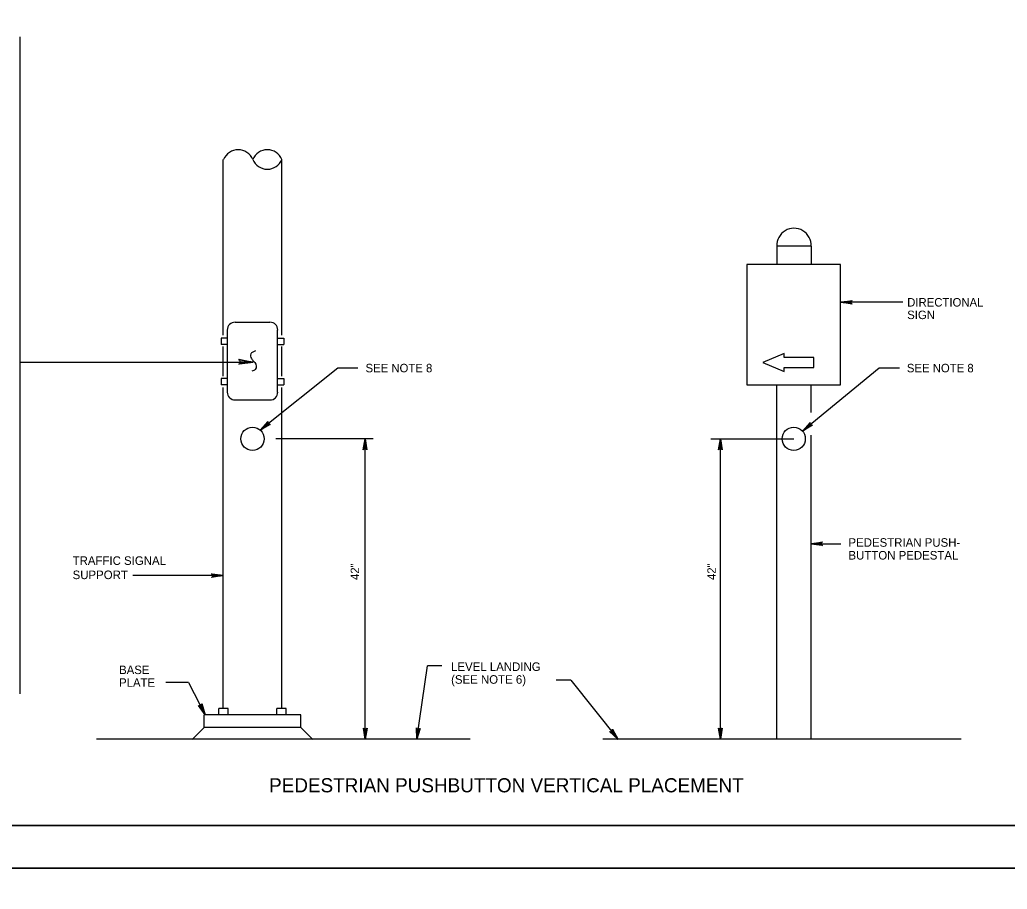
# Model space of a CAD drawing. Extents: x -344 to 940, y 22 to 1233.
# Drawn here: x 262.3 to 611.7, y 608.7 to 916.3 of the extents above; entities that cross this region are included whole.
import ezdxf

# ---------------------------------------------------------------- set-up
doc = ezdxf.new("R2010")
doc.units = 0
for name, color, linetype in [('1', 7, 'Continuous'), ('2', 7, 'Continuous'), ('3', 7, 'Continuous'), ('Default', 7, 'Continuous'), ('PLT-BNDY', 7, 'Continuous')]:
    doc.layers.add(name, color=color, linetype=linetype)

# ---------------------------------------------------------------- blocks, each defined once
blk = doc.blocks.new('RARROW')
at = {"layer": '3'}
blk.add_lwpolyline([(-2.937125, 0.36875), (-2.82775, 0.156125), (0, 0), (-2.937125, 0.36875), (-3.08775, 0.497625), (0, 0), (-2.8255, -0.13975), (-2.928625, -0.350125), (0, 0), (-3.08775, -0.490625), (-2.928625, -0.350125)], dxfattribs=at)

msp = doc.modelspace()

# ---------------------------------------------------------------- linework, layer by layer
at = {"layer": '1'}
for p, q in [((861.86, 631.17), (75.86, 631.17)), ((75.86, 631.17), (661.86, 631.17))]:
    msp.add_line(p, q, dxfattribs=at)
at = {"layer": '2'}
for p, q in [((262.33, 910.3), (262.33, 677.76)), ((334.29, 804.68), (334.29, 866.81)), ((355.04, 804.68), (355.04, 866.81)), ((530.2, 836.15), (530.2, 829.69)), ((542.29, 836.15), (530.2, 836.15)), ((542.29, 836.15), (542.29, 829.69)), ((552.75, 829.69), (519.63, 829.69)), ((519.63, 829.69), (519.63, 787.1)), ((552.75, 787.1), (552.75, 829.69)), ((350.79, 809.18), (338.54, 809.18)), ((335.79, 803.68), (333.54, 803.68)), ((333.54, 803.68), (333.54, 801.43)), ((335.79, 784.43), (335.79, 806.43)), ((353.54, 784.43), (353.54, 806.43)), ((353.54, 803.68), (355.79, 803.68)), ((355.79, 803.68), (355.79, 801.43)), ((335.79, 801.43), (333.54, 801.43)), ((334.29, 790.18), (334.29, 800.68)), ((353.54, 801.43), (355.79, 801.43)), ((355.04, 790.18), (355.04, 800.68)), ((262.33, 795.18), (344.91, 795.18)), ((374.85, 792.99), (347.38, 771.15)), ((382, 792.99), (374.85, 792.99)), ((566.39, 792.99), (539.22, 770.78)), ((573.54, 792.99), (566.39, 792.99)), ((335.79, 789.43), (333.54, 789.43)), ((333.54, 789.43), (333.54, 787.18)), ((335.79, 787.18), (333.54, 787.18)), ((334.29, 672.68), (334.29, 786.18)), ((353.54, 789.43), (355.79, 789.43)), ((353.54, 787.18), (355.79, 787.18)), ((355.04, 672.68), (355.04, 786.18)), ((355.79, 789.43), (355.79, 787.18)), ((519.63, 787.1), (552.75, 787.1)), ((530.2, 661.81), (530.2, 787.1)), ((542.29, 777.32), (542.29, 787.1)), ((350.79, 781.68), (338.54, 781.68)), ((542.29, 661.81), (542.29, 769.34)), ((387.35, 768.04), (352.97, 768.04)), ((384.54, 661.81), (384.54, 768.04)), ((506.89, 768.04), (536.17, 768.04)), ((510.22, 661.81), (510.22, 768.04)), ((542.29, 730.92), (552.81, 730.92)), ((334.29, 719.66), (302.3, 719.66)), ((402.79, 661.81), (406.54, 687.68)), ((411.66, 687.68), (406.54, 687.68)), ((322.06, 681.88), (314.03, 681.88)), ((322.06, 681.88), (327.99, 670.43)), ((457.29, 682.61), (452.17, 682.61)), ((457.29, 682.61), (474.06, 661.71)), ((336.04, 672.68), (332.79, 672.68)), ((332.79, 670.43), (332.79, 672.68)), ((336.04, 670.43), (336.04, 672.68)), ((356.54, 672.68), (353.29, 672.68)), ((353.29, 670.43), (353.29, 672.68)), ((356.54, 670.43), (356.54, 672.68)), ((327.54, 665.93), (327.54, 670.43)), ((361.79, 670.43), (327.54, 670.43)), ((361.79, 665.93), (361.79, 670.43)), ((327.54, 665.93), (323.29, 661.68)), ((361.79, 665.93), (327.54, 665.93)), ((361.79, 665.93), (366.04, 661.68)), ((421.67, 661.81), (289.51, 661.81)), ((595.39, 661.81), (468.65, 661.81))]:
    msp.add_line(p, q, dxfattribs=at)
for points in [[(556.61, 815.86), (556.47, 816.14), (552.75, 816.34), (556.61, 815.86), (556.81, 815.69), (552.75, 816.34), (556.47, 816.52), (556.6, 816.8), (552.75, 816.34), (556.81, 816.99), (556.6, 816.8)], [(340.04, 795.81), (340.16, 795.43), (344.91, 795.18), (340.04, 795.81), (339.79, 796.18), (344.91, 795.18), (340.29, 794.93), (340.04, 794.56), (344.91, 795.18), (339.79, 794.43), (340.04, 794.56)], [(350.7, 773.17), (350.42, 773.3), (347.38, 771.15), (350.7, 773.17), (350.96, 773.16), (347.38, 771.15), (350.17, 773.6), (350.11, 773.9), (347.38, 771.15), (350.16, 774.18), (350.11, 773.9)], [(542.51, 772.84), (542.22, 772.97), (539.22, 770.78), (542.51, 772.84), (542.77, 772.84), (539.22, 770.78), (541.97, 773.27), (541.9, 773.57), (539.22, 770.78), (541.95, 773.84), (541.9, 773.57)], [(546.15, 730.44), (546, 730.72), (542.29, 730.92), (546.15, 730.44), (546.34, 730.27), (542.29, 730.92), (546, 731.11), (546.13, 731.38), (542.29, 730.92), (546.34, 731.57), (546.13, 731.38)], [(330.43, 720.14), (330.57, 719.86), (334.29, 719.66), (330.43, 720.14), (330.23, 720.31), (334.29, 719.66), (330.58, 719.47), (330.44, 719.2), (334.29, 719.66), (330.23, 719.01), (330.44, 719.2)], [(326.65, 674.08), (326.47, 673.83), (327.99, 670.43), (326.65, 674.08), (326.71, 674.34), (327.99, 670.43), (326.12, 673.64), (325.81, 673.64), (327.99, 670.43), (325.55, 673.74), (325.81, 673.64)], [(472.02, 665.02), (471.89, 664.74), (474.06, 661.71), (472.02, 665.02), (472.03, 665.28), (474.06, 661.71), (471.59, 664.49), (471.29, 664.42), (474.06, 661.71), (471.01, 664.47), (471.29, 664.42)]]:
    msp.add_lwpolyline(points, dxfattribs=at)
for centre, radius, start, end in [((339.61, 864.72), 5.59, 22.6622, 157.3378), ((349.92, 864.72), 5.59, 22.6622, 157.3378), ((349.92, 869.03), 5.59, 202.6622, 337.3378), ((338.5, 806.54), 2.75, 90, 180), ((350.87, 806.54), 2.75, 0, 90), ((338.5, 784.54), 2.75, 180, 270), ((350.87, 784.54), 2.75, 270, 0)]:
    msp.add_arc(centre, radius, start, end, dxfattribs=at)
msp.add_spline([(345.79, 799.18), (344.79, 798.68), (344.04, 798.06), (344.29, 796.43), (345.04, 795.56), (345.54, 795.06), (345.66, 792.56), (344.41, 791.93)], degree=3, dxfattribs=at)
at = {"layer": 'Default'}
msp.add_line((574.82, 816.34), (552.75, 816.34), dxfattribs=at)
msp.add_lwpolyline([(525.25, 795.03), (532.82, 791.82), (532.82, 793.23), (543.28, 793.23), (543.28, 796.83), (532.82, 796.83), (532.82, 798.24)], close=True, dxfattribs=at)
for centre in [(344.68, 768.04), (536.17, 768.04)]:
    msp.add_circle(centre, 4.11, dxfattribs=at)
msp.add_arc((536.25, 836.49), 6.06, 356.7918, 183.2082, dxfattribs=at)
at = {"layer": 'PLT-BNDY'}
for points in [[(35.86, 1210.17), (876.86, 1210.17), (876.86, 616.17), (35.86, 616.17)], [(35.86, 616.17), (876.86, 616.17), (876.86, 22.17), (35.86, 22.17)]]:
    msp.add_lwpolyline(points, close=True, dxfattribs=at)

# ---------------------------------------------------------------- block references
at = {"layer": '2', "xscale": 1.2574347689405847, "yscale": 1.3092961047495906}
for p, rotation in [((384.54, 768.04), 89.99999999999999), ((510.22, 768.04), 89.99999999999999), ((384.54, 661.81), -90.00000000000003), ((402.79, 661.81), -97.89944095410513), ((510.22, 661.81), -90.00000000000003)]:
    msp.add_blockref('RARROW', p, dxfattribs=dict(at, rotation=rotation))

# ---------------------------------------------------------------- texts
at = {"layer": '2'}
for s, height, p in [('DIRECTIONAL', 3, (576.32, 814.84)), ('SIGN', 3, (576.32, 810.4)), ('SEE NOTE 8', 3, (384.67, 791.57)), ('SEE NOTE 8', 3, (576.21, 791.57)), ('PEDESTRIAN PUSH-', 3.0248, (555.54, 729.85)), ('BUTTON PEDESTAL', 3.0248, (555.54, 725.32)), ('TRAFFIC SIGNAL', 3.0248, (281.03, 723.43)), ('SUPPORT', 3.025, (281.03, 718.4)), ('LEVEL LANDING', 3.0248, (414.94, 685.91)), ('BASE', 3, (297.49, 684.8)), ('PLATE', 3, (297.49, 680.3)), ('(SEE NOTE 6)', 3.0248, (414.94, 681.38)), ('PEDESTRIAN PUSHBUTTON VERTICAL PLACEMENT', 5, (350.55, 642.96))]:
    msp.add_text(s, height=height, dxfattribs=at).set_placement(p)
for p in [(382.4, 718.08), (508.61, 718.08)]:
    msp.add_text('42"', height=3, rotation=90, dxfattribs=at).set_placement(p)

doc.saveas('drawing.dxf')
